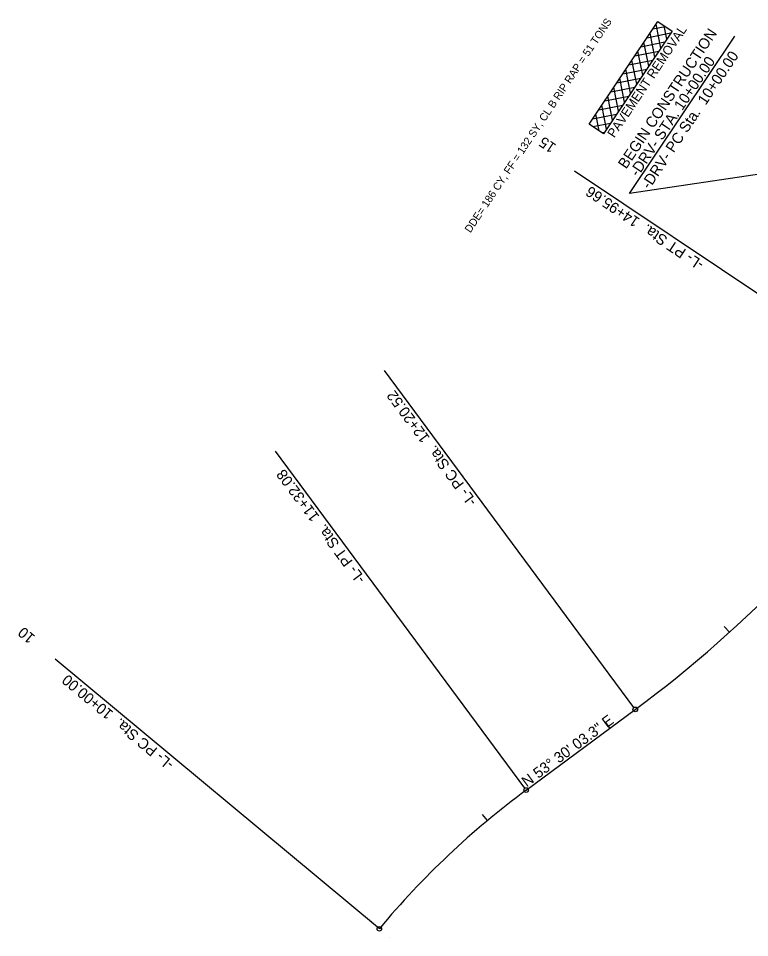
# Model space of a CAD drawing. Extents: x 1716813 to 1718091, y 800228 to 801730.
# Drawn here: x 1716813 to 1717290, y 800492 to 801091 of the extents above; entities that cross this region are included whole.
import ezdxf

# ---------------------------------------------------------------- set-up
doc = ezdxf.new("R2010")
doc.units = 0
for name, color, linetype in [('Prop Dimension', 7, 'Continuous'), ('Prop DSN Text', 7, 'Continuous'), ('Prop Hatching', 7, 'Continuous'), ('Prop Horizontal Alignment', 7, 'Continuous'), ('Prop Horizontal Alignment Direction Label', 7, 'Continuous'), ('Prop Horizontal Alignment Station Label', 7, 'Continuous'), ('Prop Horizontal Alignment Tick Label', 7, 'Continuous'), ('Prop Horizontal Alignment Tick Large', 7, 'Continuous'), ('Prop Horizontal Alignment Tick Small', 7, 'Continuous'), ('Prop Superelevation Label', 7, 'Continuous')]:
    doc.layers.add(name, color=color, linetype=linetype)

msp = doc.modelspace()

# ---------------------------------------------------------------- linework, layer by layer
at = {"layer": 'Prop Hatching'}
for p, q in [((1717185.41, 801022.13), (1717230.23, 801089.1)), ((1717232.19, 801071.72), (1717229.09, 801087.38)), ((1717230.23, 801089.1), (1717239.62, 801082.82)), ((1717239.62, 801082.82), (1717194.8, 801015.85)), ((1717223.15, 801078.51), (1717238.81, 801081.61)), ((1717228.26, 801065.84), (1717225.15, 801081.51)), ((1717227.08, 801084.39), (1717234.94, 801085.94)), ((1717236.12, 801077.6), (1717234.4, 801086.31)), ((1717219.22, 801072.63), (1717234.88, 801075.74)), ((1717224.32, 801059.97), (1717221.22, 801075.63)), ((1717215.28, 801066.76), (1717230.94, 801069.86)), ((1717220.39, 801054.09), (1717217.29, 801069.75)), ((1717211.35, 801060.88), (1717227.01, 801063.98)), ((1717216.46, 801048.22), (1717213.35, 801063.88)), ((1717207.42, 801055), (1717223.08, 801058.11)), ((1717212.52, 801042.34), (1717209.42, 801058)), ((1717203.48, 801049.13), (1717219.14, 801052.23)), ((1717208.59, 801036.46), (1717205.49, 801052.12)), ((1717199.55, 801043.25), (1717215.21, 801046.35)), ((1717204.66, 801030.59), (1717201.55, 801046.25)), ((1717195.62, 801037.38), (1717211.28, 801040.48)), ((1717200.72, 801024.71), (1717197.62, 801040.37)), ((1717191.68, 801031.5), (1717207.35, 801034.6)), ((1717196.79, 801018.83), (1717193.69, 801034.5)), ((1717187.75, 801025.62), (1717203.41, 801028.73)), ((1717191.9, 801017.79), (1717189.76, 801028.62)), ((1717194.8, 801015.85), (1717185.41, 801022.13)), ((1717187.8, 801020.54), (1717199.48, 801022.85)), ((1717193.68, 801016.6), (1717195.55, 801016.97))]:
    msp.add_line(p, q, dxfattribs=at)
at = {"layer": 'Prop Horizontal Alignment'}
msp.add_line((1717144.42, 800587.78), (1717215.52, 800640.38), dxfattribs=at)
for centre, radius, start, end in [((1716739.67, 801283.48), 800, 306.49907, 326.20506), ((1717471.57, 800145.65), 550, 126.49907, 140.25789)]:
    msp.add_arc(centre, radius, start, end, dxfattribs=at)
at = {"layer": 'Prop Horizontal Alignment Station Label'}
for p, q in [((1717211.72, 800976.91), (1717280.47, 801079.63)), ((1717355.3, 800998.42), (1717211.72, 800976.91)), ((1717403.25, 800839.33), (1717175.96, 800991.46)), ((1717214.63, 800641.59), (1717051.94, 800861.45)), ((1717143.53, 800588.98), (1716980.85, 800808.84)), ((1717047.5, 800498.24), (1716837.2, 800673.1))]:
    msp.add_line(p, q, dxfattribs=at)
for centre in [(1717215.52, 800640.38), (1717144.42, 800587.78), (1717048.66, 800497.28)]:
    msp.add_circle(centre, 1.5, dxfattribs=at)
at = {"layer": 'Prop Horizontal Alignment Tick Large'}
msp.add_line((1717048.66, 800497.28), (1717042.5, 800502.4), dxfattribs=at)
at = {"layer": 'Prop Horizontal Alignment Tick Small'}
for p, q in [((1717276.96, 800690.75), (1717273.6, 800694.46)), ((1717199.02, 800628.18), (1717196.05, 800632.2)), ((1717119.21, 800567.96), (1717116.01, 800571.8))]:
    msp.add_line(p, q, dxfattribs=at)
at = {"layer": 'Prop Superelevation Label'}
msp.add_line((1717055.58, 800491.53), (1717055.58, 800491.53), dxfattribs=at)

# ---------------------------------------------------------------- texts
at = {"layer": 'Prop Dimension'}
for s, height, p in [('DDE= 186 CY, FF = 132 SY, CL B RIP RAP = 51 TONS', 5, (1717108.02, 800950.9)), ('BEGIN CONSTRUCTION', 7, (1717209.61, 800992.48)), ('-DRV- STA. 10+00.00', 7, (1717217.23, 800987.38))]:
    msp.add_text(s, height=height, rotation=56.20506, dxfattribs=at).set_placement(p)
at = {"layer": 'Prop DSN Text'}
msp.add_text('PAVEMENT REMOVAL', height=6, rotation=56.20506, dxfattribs=at).set_placement((1717201.84, 801012.82))
at = {"layer": 'Prop Horizontal Alignment Direction Label'}
msp.add_text('N 53%%d 30\' 03.3" E', height=7, rotation=36.49907, dxfattribs=at).set_placement((1717144.76, 800589.43))
at = {"layer": 'Prop Horizontal Alignment Station Label'}
for s, rotation, p in [('-DRV- PC Sta.  10+00.00', 56.20506, (1717224.71, 800979.25)), ('-L- PT Sta.  14+95.66', 146.20506, (1717260.94, 800932.18)), ('-L- PC Sta.  12+20.52', 126.49907, (1717112.58, 800776.13)), ('-L- PT Sta.  11+32.08', 126.49907, (1717039.98, 800725.57)), ('-L- PC Sta.  10+00.00', 140.25789, (1716915.25, 800605.61))]:
    msp.add_text(s, height=7, rotation=rotation, dxfattribs=at).set_placement(p)
at = {"layer": 'Prop Horizontal Alignment Tick Label'}
for s, rotation, p in [('15', 146.20506, (1717164.48, 801008.57)), ('10', 140.25789, (1716824.72, 800688.03))]:
    msp.add_text(s, height=7, rotation=rotation, dxfattribs=at).set_placement(p)

doc.saveas('drawing.dxf')
